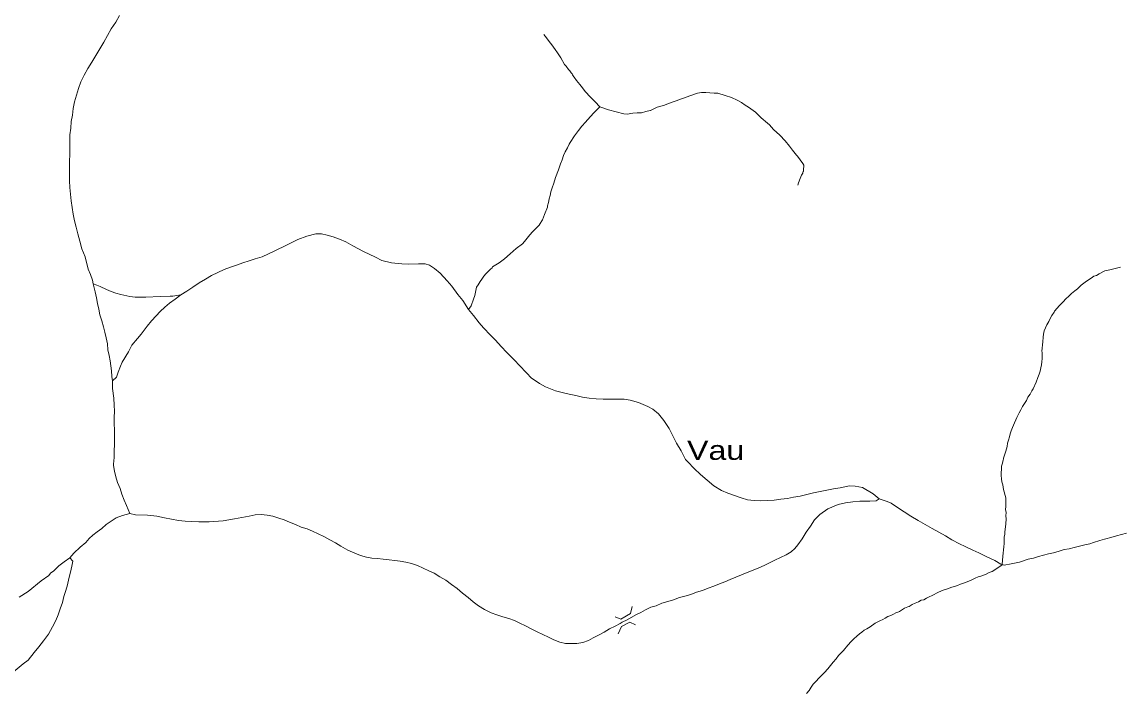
# Model space of a CAD drawing. Extents: x 781.9 to 808.1, y 7453.3 to 7481.5.
# Drawn here: x 789.499 to 794.083, y 7476.163 to 7478.95 of the extents above; entities that cross this region are included whole.
import ezdxf

# ---------------------------------------------------------------- set-up
doc = ezdxf.new("R2010")
doc.units = 0
doc.header["$LTSCALE"] = 0.032
doc.linetypes.add('LONG_DASHED', pattern=[7.5, 6, -1.5])
doc.linetypes.add('MEDIUM_DASHED', pattern=[4.5, 3, -1.5])
for name, color, linetype, lineweight in [('11', 7, 'Continuous', 13), ('32', 7, 'MEDIUM_DASHED', 13), ('5', 7, 'LONG_DASHED', 13), ('6', 7, 'MEDIUM_DASHED', 13)]:
    doc.layers.add(name, color=color, linetype=linetype, lineweight=lineweight)
doc.layers.add('61', color=7, linetype='Continuous')

msp = doc.modelspace()

# ---------------------------------------------------------------- linework, layer by layer
at = {"layer": '11'}
for points in [[(792.0367, 7476.5188), (792.0304, 7476.4889), (791.9907, 7476.4659), (791.9668, 7476.4746)], [(791.9791, 7476.4046), (791.9928, 7476.4351), (792.027, 7476.453), (792.0513, 7476.4421)]]:
    msp.add_lwpolyline(points, dxfattribs=at)
at = {"layer": '32'}
msp.add_lwpolyline([(792.2223, 7477.1981), (792.1915, 7477.2586), (792.1687, 7477.2917), (792.1471, 7477.3202), (792.1231, 7477.3396), (792.1025, 7477.3499)], dxfattribs=at)
at = {"layer": '5'}
for points in [[(789.9045, 7478.9762), (789.8892, 7478.9487), (789.8705, 7478.9211), (789.8551, 7478.8935), (789.8389, 7478.866), (789.8235, 7478.8384), (789.8057, 7478.8108), (789.7895, 7478.7833), (789.7732, 7478.7557), (789.7578, 7478.7281), (789.7433, 7478.7006), (789.7335, 7478.673), (789.7262, 7478.6454), (789.7173, 7478.6179), (789.7116, 7478.5903), (789.7092, 7478.5627), (789.7042, 7478.5352), (789.7019, 7478.5076), (789.6987, 7478.48), (789.6987, 7478.4541), (789.6979, 7478.4265), (789.6979, 7478.399), (789.6963, 7478.3714), (789.6971, 7478.3438), (789.6963, 7478.3163), (789.6971, 7478.2887)], [(789.6971, 7478.2887), (789.6987, 7478.261), (789.7011, 7478.2336), (789.7043, 7478.206), (789.7084, 7478.1784), (789.7125, 7478.1509), (789.7173, 7478.1233)], [(789.7173, 7478.1233), (789.7246, 7478.0957), (789.7311, 7478.0682), (789.74, 7478.0374), (789.7481, 7478.0066), (789.7481, 7478.0057), (789.7618, 7477.9729), (789.7741, 7477.9222), (789.7838, 7477.8995), (789.7927, 7477.8752), (789.7956, 7477.8604)], [(791.3567, 7477.7544), (791.3324, 7477.7909), (791.3121, 7477.8168), (791.2877, 7477.8509), (791.2683, 7477.8735), (791.2387, 7477.9047), (791.2155, 7477.9247), (791.1939, 7477.9383), (791.1763, 7477.9431), (791.1491, 7477.9439), (791.1075, 7477.9423), (791.0795, 7477.9431), (791.0355, 7477.9479), (790.9963, 7477.9583), (790.9691, 7477.9711), (790.9203, 7477.9951), (790.8747, 7478.0183), (790.8459, 7478.0349), (790.82, 7478.0463), (790.794, 7478.056), (790.7681, 7478.0633), (790.7449, 7478.0681), (790.7217, 7478.0681), (790.6833, 7478.0593), (790.6465, 7478.0449), (790.6025, 7478.0225), (790.5481, 7477.9961), (790.4985, 7477.9729), (790.4697, 7477.9652), (790.4438, 7477.9564), (790.4178, 7477.9474), (790.3919, 7477.9384), (790.366, 7477.9303), (790.34, 7477.9206), (790.3141, 7477.9076), (790.2881, 7477.8946), (790.2622, 7477.88), (790.2362, 7477.8647), (790.2103, 7477.846), (790.1851, 7477.8298), (790.16, 7477.8144)], [(789.7956, 7477.8604), (789.8032, 7477.8266), (789.809, 7477.8022), (789.813, 7477.7794), (789.8187, 7477.7552), (789.8235, 7477.7309), (789.8308, 7477.7066), (789.8381, 7477.6823), (789.8438, 7477.6596), (789.8495, 7477.6352), (789.8543, 7477.6109), (789.8568, 7477.5866), (789.8616, 7477.5623), (789.8665, 7477.5396), (789.8714, 7477.4988), (789.8722, 7477.4756), (789.8758, 7477.4568)], [(790.16, 7477.8144), (790.1357, 7477.7966), (790.113, 7477.7803), (790.0927, 7477.7633), (790.074, 7477.7455), (790.057, 7477.7268), (790.0382, 7477.706), (790.0198, 7477.6844), (789.995, 7477.6508), (789.9791, 7477.6328), (789.9559, 7477.6056), (789.9423, 7477.5776), (789.9159, 7477.5352), (789.9086, 7477.5184), (789.8998, 7477.4928), (789.8918, 7477.472), (789.8758, 7477.4568)], [(792.1025, 7477.3499), (792.0637, 7477.367), (792.0295, 7477.3762), (792.0044, 7477.3808), (791.9747, 7477.3808), (791.9161, 7477.3806), (791.8869, 7477.3822), (791.8578, 7477.3847), (791.8302, 7477.3895), (791.8026, 7477.396), (791.7751, 7477.4009), (791.7459, 7477.409), (791.7183, 7477.4147), (791.6767, 7477.4315), (791.6519, 7477.4459), (791.6215, 7477.4667), (791.6186, 7477.4674), (791.5975, 7477.4901), (791.5683, 7477.5201), (791.5472, 7477.5428), (791.5156, 7477.5744), (791.4921, 7477.5995), (791.4686, 7477.6255), (791.4483, 7477.6466), (791.4191, 7477.6774), (791.4005, 7477.6984), (791.3769, 7477.7293), (791.3567, 7477.7544)], [(789.8758, 7477.4568), (789.8758, 7477.4256), (789.8807, 7477.3848), (789.8827, 7477.3563), (789.8835, 7477.3304), (789.8819, 7477.3044), (789.8828, 7477.2785), (789.8844, 7477.2525), (789.8835, 7477.2266), (789.8844, 7477.1938), (789.8827, 7477.1642), (789.8828, 7477.1322)], [(792.6004, 7476.959), (792.5728, 7476.9574), (792.5453, 7476.959), (792.5177, 7476.9623), (792.4902, 7476.9704), (792.4626, 7476.9793), (792.435, 7476.9898), (792.4091, 7477.0012), (792.3774, 7477.0207), (792.349, 7477.0434), (792.3215, 7477.0677), (792.2947, 7477.092), (792.2688, 7477.1195), (792.2599, 7477.1293), (792.2415, 7477.1653), (792.2223, 7477.1981)], [(789.8828, 7477.1322), (789.8811, 7477.1301), (789.8803, 7477.105), (789.8835, 7477.0807), (789.89, 7477.058), (789.8965, 7477.0336), (789.907, 7477.0093)], [(789.907, 7477.0093), (789.9143, 7476.985), (789.9241, 7476.9607), (789.9338, 7476.938), (789.9475, 7476.9044)], [(793.0642, 7476.9667), (793.0394, 7476.9875), (792.9954, 7477.0131), (792.9653, 7477.019), (792.9417, 7477.0207), (792.902, 7477.0125), (792.8745, 7477.0077), (792.8469, 7477.0028), (792.8193, 7476.9963), (792.7918, 7476.9907), (792.7642, 7476.9842)], [(792.401, 7476.612), (792.4228, 7476.6209), (792.4447, 7476.6307), (792.4691, 7476.6404), (792.4918, 7476.6501), (792.5161, 7476.6599), (792.5404, 7476.6688), (792.5639, 7476.6793), (792.5858, 7476.689), (792.6085, 7476.6996), (792.6312, 7476.7109), (792.6547, 7476.7215), (792.6782, 7476.7336), (792.6993, 7476.7458), (792.7147, 7476.7588), (792.7269, 7476.775), (792.7447, 7476.7993), (792.7609, 7476.8269), (792.7788, 7476.8528), (792.7958, 7476.8788), (792.8177, 7476.9006), (792.8274, 7476.9079), (792.842, 7476.9169), (792.8517, 7476.925), (792.8939, 7476.942), (792.9247, 7476.9493), (792.9555, 7476.9534), (792.9847, 7476.9566), (793.0155, 7476.9566), (793.0254, 7476.957), (793.0527, 7476.9578), (793.0642, 7476.9667)], [(792.7642, 7476.9842), (792.7366, 7476.9777), (792.7091, 7476.9736), (792.6831, 7476.968), (792.6555, 7476.9647), (792.628, 7476.9607), (792.6004, 7476.959)], [(793.5767, 7476.6926), (793.5708, 7476.6942), (793.5463, 7476.7102), (793.5071, 7476.727), (793.4793, 7476.7409), (793.4549, 7476.7523), (793.4225, 7476.7677), (793.399, 7476.779), (793.3666, 7476.7952), (793.3406, 7476.8115), (793.3131, 7476.8269), (793.2847, 7476.8423), (793.2563, 7476.8593), (793.2271, 7476.8755), (793.1971, 7476.8934), (793.1687, 7476.912), (793.1411, 7476.9299), (793.1144, 7476.9477), (793.0978, 7476.9547), (793.0642, 7476.9667)], [(789.9475, 7476.9044), (789.9168, 7476.8967), (789.8908, 7476.8877), (789.8697, 7476.8731), (789.8495, 7476.8593), (789.8308, 7476.8431), (789.8114, 7476.8293), (789.7935, 7476.8147), (789.7781, 7476.8009), (789.7644, 7476.7847), (789.7408, 7476.7645), (789.7144, 7476.7405), (789.6984, 7476.7205)], [(789.9475, 7476.9044), (789.9707, 7476.8996), (790.0211, 7476.898), (790.0604, 7476.894), (790.0919, 7476.8869), (790.1211, 7476.882), (790.1503, 7476.8755), (790.1779, 7476.8731), (790.2054, 7476.8715), (790.2346, 7476.8707), (790.2779, 7476.8699), (790.3356, 7476.8739), (790.3829, 7476.8827), (790.4438, 7476.8939), (790.4697, 7476.899), (790.4941, 7476.9007), (790.5184, 7476.8982), (790.5427, 7476.8942), (790.567, 7476.8861), (790.5897, 7476.8788), (790.6124, 7476.869), (790.6367, 7476.8593), (790.6611, 7476.8488), (790.6854, 7476.8407), (790.7081, 7476.8309), (790.7308, 7476.8204), (790.7551, 7476.809), (790.7794, 7476.796), (790.8038, 7476.7831), (790.8248, 7476.7693), (790.854, 7476.7531), (790.8832, 7476.7401), (790.9075, 7476.7304), (790.9319, 7476.7231), (790.9546, 7476.7199), (790.9773, 7476.7174), (791.0016, 7476.715), (791.0259, 7476.7117), (791.0502, 7476.7093), (791.0729, 7476.7069), (791.0956, 7476.7028), (791.12, 7476.6964), (791.1443, 7476.689), (791.1686, 7476.6777), (791.1913, 7476.6671), (791.214, 7476.6566), (791.2375, 7476.642), (791.2626, 7476.6274), (791.2853, 7476.6096), (791.3088, 7476.5926), (791.3315, 7476.5731), (791.355, 7476.5561), (791.3762, 7476.5382), (791.398, 7476.5212), (791.4224, 7476.505), (791.4508, 7476.492), (791.475, 7476.4831), (791.4994, 7476.475), (791.5237, 7476.4677), (791.548, 7476.4596), (791.5707, 7476.449), (791.5934, 7476.4377), (791.6178, 7476.4255), (791.6421, 7476.4134), (791.6664, 7476.402), (791.6891, 7476.3899), (791.7118, 7476.3793), (791.7361, 7476.3704), (791.7605, 7476.3647), (791.7848, 7476.3639), (791.8075, 7476.3647), (791.8318, 7476.3688), (791.8553, 7476.3761), (791.8756, 7476.3874), (791.8975, 7476.3988), (791.9202, 7476.4109), (791.9437, 7476.4247), (791.9664, 7476.4361), (791.9875, 7476.4474), (791.9964, 7476.4523), (792.0159, 7476.4628), (792.0523, 7476.4831), (792.0734, 7476.4928), (792.0929, 7476.5042), (792.1147, 7476.5155), (792.1367, 7476.5212), (792.161, 7476.5317), (792.1853, 7476.5391), (792.2096, 7476.5464), (792.234, 7476.5553), (792.2567, 7476.5617)], [(794.0938, 7476.8228), (794.0728, 7476.818), (794.0517, 7476.8123), (794.029, 7476.8058), (794.0079, 7476.8001), (794.0022, 7476.7986), (793.9827, 7476.7928), (793.956, 7476.7839), (793.9414, 7476.779), (793.9203, 7476.7742), (793.8976, 7476.7685), (793.8766, 7476.7636), (793.8555, 7476.758), (793.8344, 7476.7555), (793.8133, 7476.749), (793.7906, 7476.7417), (793.7695, 7476.7377), (793.7485, 7476.732), (793.7274, 7476.7255), (793.7063, 7476.7199), (793.6852, 7476.715), (793.6484, 7476.703), (793.614, 7476.695), (793.5852, 7476.6902), (793.5767, 7476.6926)], [(789.6984, 7476.7205), (789.7109, 7476.7066), (789.7068, 7476.6866), (789.7011, 7476.6607), (789.6946, 7476.6347), (789.6881, 7476.6088), (789.6808, 7476.5845), (789.6735, 7476.5602), (789.667, 7476.5342), (789.6581, 7476.5083), (789.65, 7476.4839), (789.6403, 7476.4596), (789.6257, 7476.4337), (789.6087, 7476.4028), (789.5892, 7476.3753), (789.5698, 7476.351), (789.5503, 7476.3274), (789.5243, 7476.295), (789.5041, 7476.2796), (789.4627, 7476.2448)], [(789.6984, 7476.7205), (789.6744, 7476.7045), (789.6528, 7476.6877), (789.6314, 7476.6663), (789.6176, 7476.6574), (789.6111, 7476.6477), (789.5795, 7476.625), (789.5244, 7476.5812), (789.4868, 7476.5564)], [(792.2567, 7476.5617), (792.281, 7476.5682), (792.3053, 7476.5771), (792.3296, 7476.5853), (792.3539, 7476.5942), (792.3766, 7476.6023), (792.401, 7476.612)]]:
    msp.add_lwpolyline(points, dxfattribs=at)
at = {"layer": '6'}
for points in [[(791.6705, 7478.8976), (791.681, 7478.8838), (791.6923, 7478.8692), (791.7029, 7478.8546), (791.7166, 7478.836), (791.7264, 7478.8222), (791.7401, 7478.8011), (791.7564, 7478.7727), (791.7621, 7478.7662), (791.7726, 7478.7525), (791.7775, 7478.7467), (791.7815, 7478.7419), (791.7831, 7478.7378), (791.7872, 7478.7346), (791.7896, 7478.7297), (791.7921, 7478.7257), (791.7949, 7478.7216), (791.7961, 7478.7208), (791.7986, 7478.7168), (791.8034, 7478.7111), (791.8058, 7478.707), (791.8196, 7478.6892), (791.8302, 7478.6754), (791.8415, 7478.6608), (791.8642, 7478.6365), (791.8828, 7478.6178), (791.9033, 7478.5965)], [(791.9033, 7478.5965), (791.9386, 7478.5845), (792.0024, 7478.5681), (792.0164, 7478.5661), (792.0397, 7478.5701), (792.0588, 7478.5716), (792.0767, 7478.5724), (792.0945, 7478.5781), (792.1123, 7478.5822), (792.1131, 7478.5822), (792.1415, 7478.596), (792.1675, 7478.6024), (792.1853, 7478.6097), (792.2031, 7478.6162), (792.221, 7478.6219), (792.2388, 7478.6292), (792.2461, 7478.6316), (792.281, 7478.6446), (792.3085, 7478.6535), (792.3264, 7478.6559), (792.3442, 7478.6559), (792.3604, 7478.6551), (792.3783, 7478.6543), (792.3937, 7478.6535), (792.4237, 7478.6446), (792.4504, 7478.6357), (792.4739, 7478.6243), (792.4918, 7478.6146), (792.508, 7478.604), (792.5218, 7478.5952), (792.5509, 7478.5741), (792.5744, 7478.5505), (792.6004, 7478.5295), (792.6093, 7478.5222), (792.6247, 7478.5027), (792.6514, 7478.4784), (792.6741, 7478.4549), (792.6912, 7478.433), (792.705, 7478.4168), (792.7212, 7478.3957), (792.7245, 7478.3917), (792.7479, 7478.3608), (792.7512, 7478.3544), (792.7504, 7478.3341), (792.7504, 7478.3276), (792.7471, 7478.326), (792.7471, 7478.3203), (792.7439, 7478.3163), (792.7414, 7478.3122), (792.7366, 7478.2984), (792.7293, 7478.2806), (792.7261, 7478.2717)], [(791.9033, 7478.5965), (791.878, 7478.5724), (791.8522, 7478.5425), (791.8439, 7478.5335), (791.8285, 7478.5165), (791.8147, 7478.4979), (791.7969, 7478.476), (791.7791, 7478.4484), (791.775, 7478.4411), (791.7685, 7478.4265), (791.758, 7478.4103), (791.7523, 7478.3941), (791.7458, 7478.377), (791.7393, 7478.3592), (791.7329, 7478.339), (791.7313, 7478.3349), (791.7191, 7478.3033), (791.7118, 7478.2798), (791.7045, 7478.2595), (791.6996, 7478.2433), (791.6956, 7478.2287), (791.6915, 7478.2141), (791.6891, 7478.1995), (791.6858, 7478.1849), (791.6851, 7478.1792), (791.6729, 7478.1493), (791.6639, 7478.1265), (791.6518, 7478.1071), (791.6518, 7478.1063), (791.6226, 7478.0762), (791.6113, 7478.0641), (791.5893, 7478.0373), (791.5813, 7478.0268), (791.5552, 7478.0071), (791.5303, 7477.9847), (791.5058, 7477.9642), (791.4834, 7477.9474), (791.4565, 7477.931), (791.4548, 7477.9271), (791.4499, 7477.923), (791.4475, 7477.9206), (791.4457, 7477.9198), (791.445, 7477.9181), (791.441, 7477.9141), (791.4394, 7477.9133), (791.4378, 7477.9117), (791.428, 7477.9019), (791.4207, 7477.8922), (791.4126, 7477.8801), (791.4053, 7477.8703), (791.3964, 7477.8566), (791.3899, 7477.8468), (791.3834, 7477.812), (791.3777, 7477.7965), (791.3677, 7477.7696), (791.3567, 7477.7544)], [(794.0685, 7477.9299), (794.0248, 7477.9191), (794.0032, 7477.9143), (793.9795, 7477.9019), (793.969, 7477.8954), (793.9576, 7477.8922), (793.9463, 7477.8841), (793.9268, 7477.8719), (793.9049, 7477.8549), (793.8984, 7477.8484), (793.8895, 7477.8403), (793.879, 7477.8314), (793.8652, 7477.8209), (793.8538, 7477.8095), (793.8416, 7477.7982), (793.8303, 7477.7852), (793.8157, 7477.7698), (793.7947, 7477.7463), (793.7922, 7477.7422), (793.7833, 7477.7293), (793.7768, 7477.7163), (793.7703, 7477.7033), (793.763, 7477.6904), (793.7573, 7477.6774), (793.7517, 7477.6644), (793.7484, 7477.6514), (793.7468, 7477.6385), (793.7452, 7477.619), (793.742, 7477.5809), (793.7427, 7477.5752), (793.7436, 7477.5623), (793.7427, 7477.5493), (793.7411, 7477.5363), (793.7395, 7477.5233), (793.7371, 7477.5104), (793.7346, 7477.4974), (793.7298, 7477.4844), (793.7249, 7477.4715), (793.7176, 7477.452), (793.7055, 7477.4236), (793.6998, 7477.4147), (793.6933, 7477.4017), (793.6836, 7477.3888), (793.6771, 7477.3758), (793.669, 7477.3628), (793.6609, 7477.3498), (793.6544, 7477.3369), (793.6471, 7477.3239), (793.6373, 7477.3044), (793.6236, 7477.2728), (793.6195, 7477.2623), (793.6146, 7477.2493), (793.6098, 7477.2363), (793.6073, 7477.2234), (793.6033, 7477.2104), (793.5992, 7477.1974), (793.5968, 7477.1844), (793.5911, 7477.165), (793.5814, 7477.1358), (793.5814, 7477.1317), (793.5806, 7477.1277), (793.5773, 7477.1147), (793.5741, 7477.1017), (793.5733, 7477.0888), (793.5717, 7477.0758), (793.5717, 7477.0628), (793.5733, 7477.0499), (793.5757, 7477.0369), (793.579, 7477.0239), (793.5822, 7477.0045), (793.5912, 7476.9696), (793.5911, 7476.9607), (793.5919, 7476.9477), (793.5911, 7476.9347), (793.5903, 7476.9218), (793.5928, 7476.9088), (793.5918, 7476.8958), (793.5928, 7476.8828), (793.5919, 7476.8618), (793.5879, 7476.8269), (793.5871, 7476.8196), (793.5854, 7476.8066), (793.5846, 7476.7937), (793.5846, 7476.7807), (793.5834, 7476.7659), (793.579, 7476.727), (793.5767, 7476.6926)], [(789.7956, 7477.8604), (789.8109, 7477.8548), (789.8242, 7477.8495), (789.8503, 7477.8363), (789.8697, 7477.8282), (789.8892, 7477.8217), (789.9103, 7477.8168), (789.9225, 7477.8136), (789.9476, 7477.8079), (789.9703, 7477.8055), (790.014, 7477.8051), (790.0738, 7477.8079), (790.1151, 7477.8091), (790.1272, 7477.8099), (790.16, 7477.8144)], [(793.5767, 7476.6926), (793.5766, 7476.6909), (793.5457, 7476.6704), (793.5344, 7476.6639), (793.5222, 7476.659), (793.5101, 7476.6525), (793.4987, 7476.6485), (793.4874, 7476.6444), (793.476, 7476.6412), (793.4647, 7476.6355)], [(793.3901, 7476.6055), (793.3787, 7476.6015), (793.3674, 7476.5982), (793.356, 7476.5942), (793.3447, 7476.5901), (793.3317, 7476.5861), (793.3123, 7476.578), (793.2855, 7476.5642), (793.2733, 7476.5585), (793.262, 7476.5528), (793.2506, 7476.5463), (793.2393, 7476.5439), (793.2279, 7476.5374), (793.215, 7476.5326), (793.202, 7476.5261), (793.189, 7476.5188), (793.1841, 7476.5171), (793.1703, 7476.5107), (793.1493, 7476.4969), (793.1469, 7476.4961), (793.1346, 7476.4912), (793.1242, 7476.4863), (793.1128, 7476.4807), (793.1014, 7476.4766), (793.0901, 7476.4693), (793.0796, 7476.4644), (793.0674, 7476.4588), (793.0487, 7476.449), (793.0277, 7476.4337), (793.0139, 7476.4255), (793.0025, 7476.419), (792.9928, 7476.4117), (792.9831, 7476.4045), (792.9725, 7476.3947), (792.9596, 7476.3842), (792.9482, 7476.372), (792.9344, 7476.3566), (792.9158, 7476.3356), (792.9076, 7476.3266), (792.8963, 7476.3137), (792.8858, 7476.2999), (792.8736, 7476.2869), (792.8622, 7476.2731), (792.8517, 7476.2593), (792.8371, 7476.2439), (792.8169, 7476.2221), (792.8136, 7476.2196), (792.8031, 7476.2074), (792.7909, 7476.1945), (792.782, 7476.1823), (792.7739, 7476.1693), (792.7625, 7476.1564)], [(793.4647, 7476.6355), (793.4582, 7476.6339), (793.4452, 7476.6266), (793.4201, 7476.6169), (793.416, 7476.6152), (793.4031, 7476.6112), (793.3901, 7476.6055)]]:
    msp.add_lwpolyline(points, dxfattribs=at)

# ---------------------------------------------------------------- texts
at = {"layer": '61', "width": 1.25}
msp.add_text('Vau', height=0.08, dxfattribs=at).set_placement((792.2656, 7477.1283))

doc.saveas('drawing.dxf')
